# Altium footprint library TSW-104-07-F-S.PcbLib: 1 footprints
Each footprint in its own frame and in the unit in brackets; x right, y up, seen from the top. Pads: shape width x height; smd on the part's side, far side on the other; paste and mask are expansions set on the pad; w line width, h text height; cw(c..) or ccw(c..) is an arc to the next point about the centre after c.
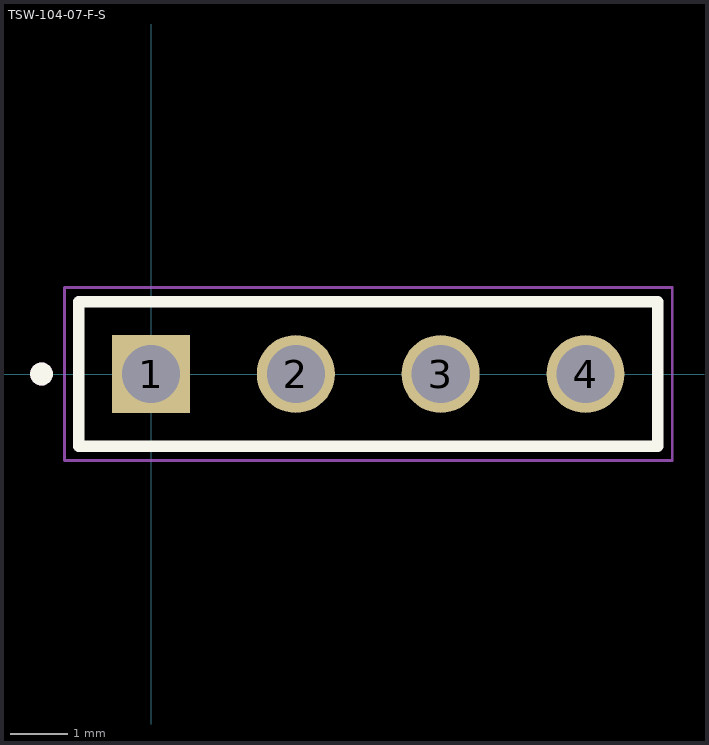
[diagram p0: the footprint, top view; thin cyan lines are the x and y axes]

## TSW-104-07-F-S [mm]
pads (4):
  rect 1.37x1.37 hole 1.02: 1(0,0)
  round 1.37 hole 1.02: 2(2.54,0) 3(5.08,0) 4(7.62,0)
Top Overlay:
  circle w0.2: c-1.92,0 r0.1
  lines w0.2: -1.27,-1.27 -1.27,1.27 8.89,1.27 8.89,-1.27 -1.27,-1.27
Mechanical 13:
  circle w0.2: c-1.92,0 r0.1
  lines w0.1: -1.27,-1.27 -1.27,1.27 8.89,1.27 8.89,-1.27 -1.27,-1.27
Mechanical 15:
  lines w0.05: -1.52,-1.52 -1.52,1.52 9.14,1.52 9.14,-1.52 -1.52,-1.52
3D body "TSW-104-07-F-S.stp": height 9.27, standoff -2.92, extent -1.487,-1.255 8.8,1.285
